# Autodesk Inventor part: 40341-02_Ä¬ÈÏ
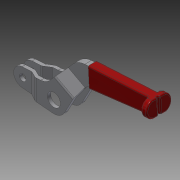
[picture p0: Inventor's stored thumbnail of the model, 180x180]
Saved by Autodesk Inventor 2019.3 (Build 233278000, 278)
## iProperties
Created: 2010-06
Part Number: 40341-02_Ä¬ÈÏ
Material: Ogólny
Document SubType Name: Modeling
Designer: CADENGINEERING4
Density: 1 g/cm^3
Appearance: Domyślna
Author: CADENGINEERING4
Revision Number: ÈÎºÎ
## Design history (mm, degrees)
feature "NONE"
node "Bryła1"
